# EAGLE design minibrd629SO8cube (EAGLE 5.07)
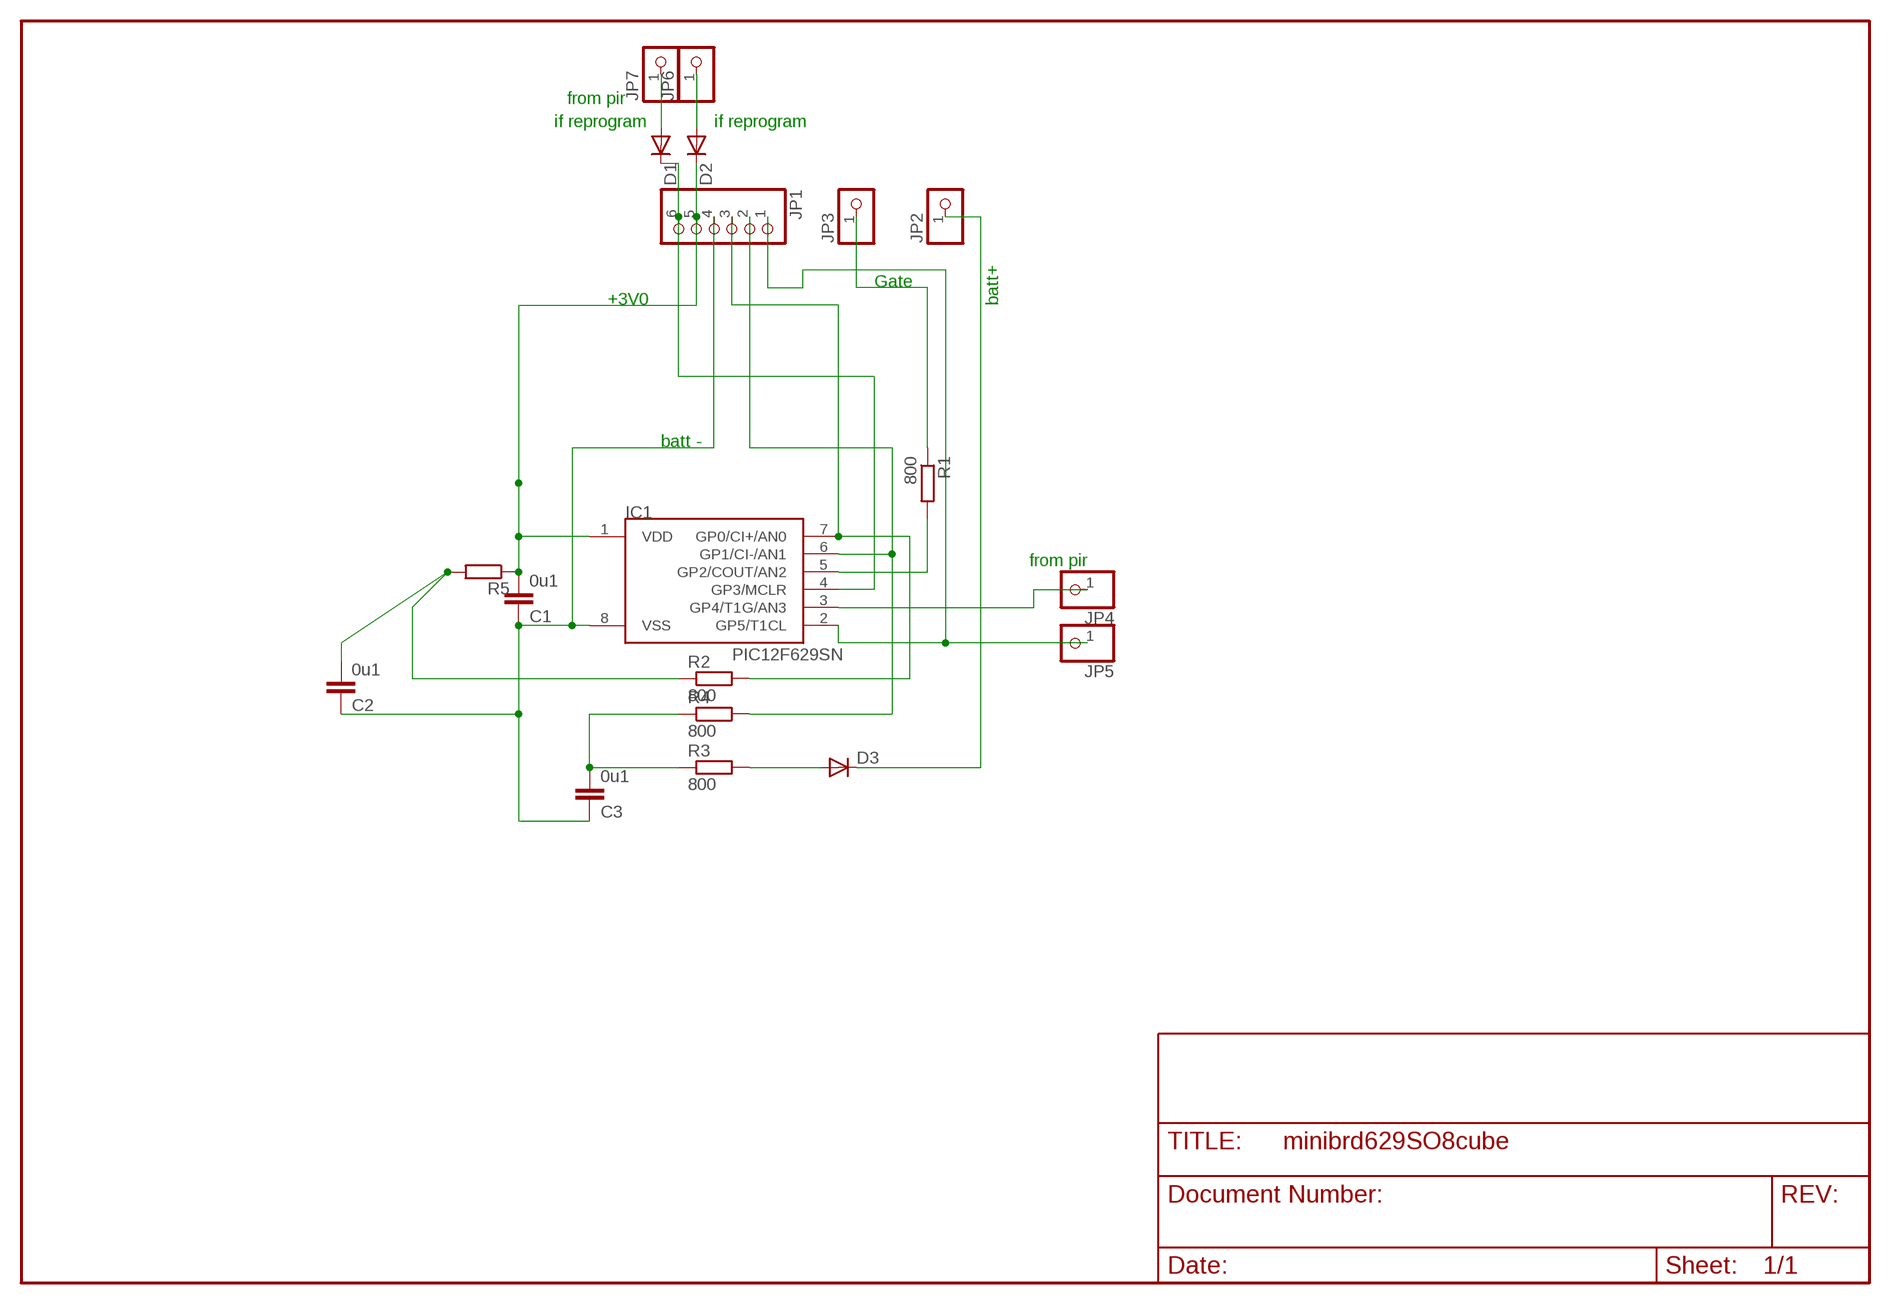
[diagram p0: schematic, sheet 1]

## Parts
C1  0u1  C-EUC1206  [C1206]
C2  0u1  C-EUC1206  [C1206]
C3  0u1  C-EUC1206  [C1206]
D1  DIODE-MINIMELF  [MINIMELF]
D2  DIODE-MINIMELF  [MINIMELF]
D3  DIODE-MINIMELF  [MINIMELF]
IC1  PIC12F629SN  [SO-08]
JP1  PINHD-1X6  [1X06BOX]
JP2  PINHD-1X1  [1X01]
JP3  PINHD-1X1  [1X01]
JP4  PINHD-1X1  [1X01]
JP5  PINHD-1X1  [1X01]
JP6  PINHD-1X1  [1X01]
JP7  PINHD-1X1  [1X01]
R1  800  R-EU_M1206  [M1206]
R2  800  R-EU_M1206  [M1206]
R3  800  R-EU_M1206  [M1206]
R4  800  R-EU_M1206  [M1206]
R5  R-EU_0613/5V  [P0613V]

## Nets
N$1: IC1.5(GP2/COUT/AN2) R1.2
N$2: D1.A JP7.1
N$3: D2.A JP6.1
N$4: IC1.7(GP0/CI+/AN0) JP1.3 R2.2
N$5: JP3.1 R1.1
N$6: C2.2 R2.1 R5.2
N$7: C3.2 R3.1 R4.1
N$8: IC1.6(GP1/CI-/AN1) JP1.2 R4.2
N$9: D3.A R3.2
N$11: IC1.2(GP5/T1CL) JP1.1 JP5.1
N$13: IC1.3(GP4/T1G/AN3) JP4.1
PIR: D1.C IC1.4(GP3/MCLR) JP1.6
V3: C1.2 D2.C IC1.1(VDD) JP1.5 R5.1
V+: D3.C JP2.1
V-: C1.1 C2.1 C3.1 IC1.8(VSS) JP1.4

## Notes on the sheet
- from pir
- if reprogram | if reprogram
- Gate
- +3V0 | batt+
- batt -
- from pir

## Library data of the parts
C1-C3 = rcl:C-EU: CAPACITOR, European symbol
D1-D3 = diode-1:DIODE-: DIODE
IC1 = microchip-3:PIC12F6*: uPC nW 1k Program Flash memory 2x Timer Comparator 10b A/D converter/ 4xIN
JP1 = pinhead:PINHD-1X6: PIN HEADER
JP2-JP7 = pinhead:PINHD-1X1: PIN HEADER
R1-R5 = rcl:R-EU_: RESISTOR, European symbol

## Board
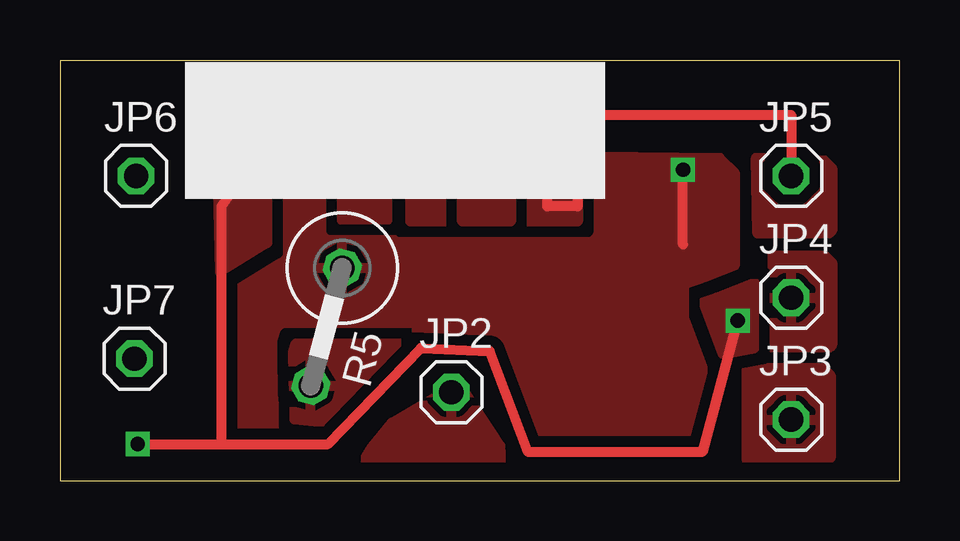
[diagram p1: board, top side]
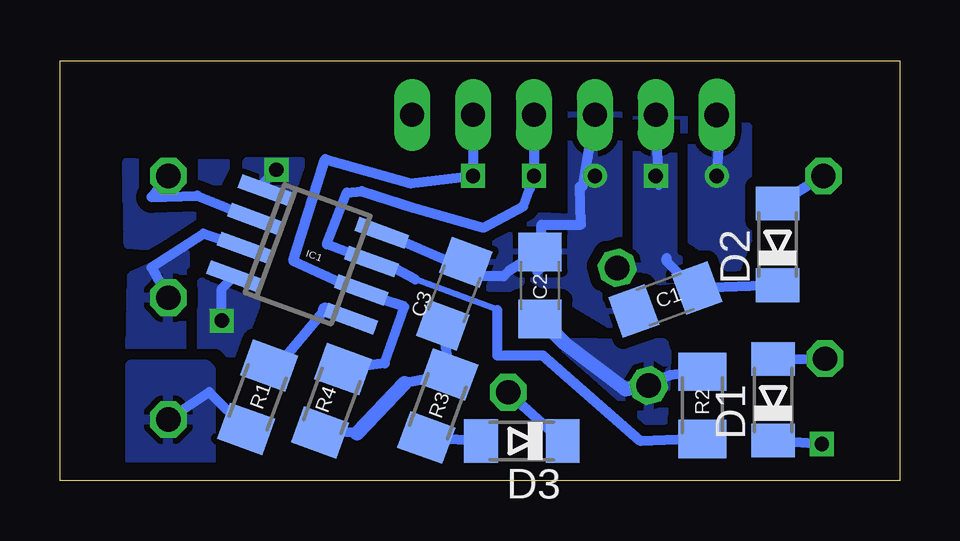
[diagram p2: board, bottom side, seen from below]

Size 35 x 17.5 mm. Coordinates in mm from the lower left corner, seen from the top.
Outline: 0,0 35,0 35,17.5 0,17.5 0,0
Copper layers (1*16): Top 0.035mm / dielectric 1.5mm / Bottom 0.035mm
Design rules "default *": minimum track width 10mil, minimum drill 24mil, track to track 18mil, track to pad 18mil, pad to pad 8mil, via to via 8mil, smd to smd 8mil, copper to edge 30mil, drill to drill 8mil, minimum pad ring 10mil, minimum via ring 8mil, stop-mask expansion 4mil, vias tented up to drill 0mil, thermal gap 10mil

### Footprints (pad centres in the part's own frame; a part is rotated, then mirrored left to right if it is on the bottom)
C1206 = smd 1.6 x 1.8: 1 -1.4,0; 2 1.4,0
MINIMELF = smd 1.4 x 1.8: A 1.7,0; C -1.7,0
SO-08 = smd 0.6 x 2.2: 1 -1.905,-2.6; 2 -0.635,-2.6; 3 0.635,-2.6; 4 1.905,-2.6; 5 1.905,2.6; 6 0.635,2.6; 7 -0.635,2.6; 8 -1.905,2.6
1X06BOX = drill 1 long: 1 -6.35,0; 2 -3.81,0; 3 -1.27,0; 4 1.27,0; 5 3.81,0 | drill 1.016 long: 6 6.35,0
1X01 = drill 1.016 octagon: 1 0,0
M1206 = smd 1.6 x 2: 1 -1.4,0; 2 1.4,0
P0613V = drill 1.016 octagon: 1 -2.54,0; 2 2.54,0

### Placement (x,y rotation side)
C1  9.76,7.54 20 bottom
C2  14.99,8.13 270 bottom
C3  18.56,7.79 250 bottom
D1  5.27,3.37 90 bottom
D2  5.08,9.84 90 bottom
D3  15.75,1.65 180 bottom
IC1  24.67,9.43 250 bottom
JP1  13.97,15.24 180 top
JP2  16.32,3.68 0 top
JP3  30.48,2.54 0 top
JP4  30.48,7.62 0 top
JP5  30.48,12.7 0 top
JP6  3.17,12.7 0 top
JP7  3.11,5.08 0 top
R1  26.76,3.47 70 bottom
R2  8.22,3.14 270 bottom
R3  19.25,3.1 250 bottom
R4  23.67,3.33 70 bottom
R5  11.11,6.41 255 top

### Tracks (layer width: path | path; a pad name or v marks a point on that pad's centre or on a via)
N$1
  Bottom 0.406: R1.2 25.97,4.7 23.94,7.11
  Bottom 0.61: 23.94,7.11 IC1.5
N$2
  Bottom 0.406: D1.A JP7.1
N$3
  Bottom 0.406: D2.A JP6.1
N$4  (via drill 0.6)
  Top 0.406: v15.24,12.7 JP1.3
  Bottom 0.254: 16.76,7.11 20.19,8.38
  Bottom 0.406: 20.19,8.38 21.02,8.83 21.91,9.08 IC1.7 23.88,9.84 23.05,12 22.42,12.06 20.26,11.37 17.34,10.54 15.68,11.43 15.43,12.13 v15.24,12.7 | 16.76,7.11 16.76,5.21 14.86,5.21 10.79,1.65 R2.2 | JP1.3 15.24,12.89
  pour Top (rank 3): 14.61,15.24 16.26,15.24 16.26,10.79 14.61,10.79
N$5
  Bottom 0.406: R1.1 28.77,3.69 JP3.1
  pour Bottom: 28.89,4.83 32.07,4.83 32.07,0.76 28.7,0.76 28.7,4.64
  pour Top (rank 2): 28.64,4.7 31.81,4.7 32.13,4.38 32.13,0.95 31.94,0.76 28.7,0.76 28.64,0.83
N$6
  Bottom 0.406: R2.1 9.59,4.38 R5.2
  Bottom 0.61: C2.2 13.97,5.71 11.43,3.81 R5.2
  pour Bottom (rank 2): 9.84,5.71 14.16,5.71 14.73,4.7 10.99,2.41 9.78,2.54 9.72,5.33
  pour Top: 9.84,5.71 14.16,5.71 14.73,4.7 10.99,2.41 9.78,2.54 9.72,5.33
N$7
  Bottom 0.406: C3.2 18.73,4.32 R3.1 20.64,4.06 | R4.1 24,2.1 22.61,1.97
  Bottom 0.61: 20.64,4.06 22.61,1.97
N$8  (via drill 0.6)
  Top 0.406: v17.78,12.7 JP1.2
  Bottom 0.406: 22.54,7.87 IC1.6 | 22.54,7.87 23.05,8.13 25.27,9.14 23.94,13.4 20.38,12.38 v17.78,12.7 | 22.54,7.87 20.64,7.24 21.46,4.89 23.3,4.64 R4.2 | JP1.2 17.78,12.51
  pour Top (rank 2): 16.76,15.24 18.8,15.24 18.8,10.79 16.76,10.79
N$9
  Bottom 0.406: D3.A R3.2
N$11
  Top 0.406: JP1.1 20.32,11.43 21.59,11.43 21.59,15.24 30.48,15.24 JP5.1
  Bottom 0.406: IC1.2 29.27,11.87 31.18,11.81 JP5.1
  pour Top (rank 3): 19.3,15.24 21.59,15.24 21.59,10.79 19.3,10.79
N$13
  Bottom 0.406: IC1.3 29.02,10.29 31.18,8.89 JP4.1
  pour Bottom (rank 3): 30.61,9.14 32,8.51 32.07,5.52 29.78,5.52 29.78,9.46
  pour Top (rank 3): 29.72,9.4 31.88,9.4 32.19,9.08 32.19,5.65 32.07,5.52 29.72,5.52 29.65,5.59
N$14
  pour Bottom: 28.07,13.21 29.08,11.11 31.43,9.78 32.13,9.84 32.19,13.27 31.24,13.21
  pour Top: 29.02,13.46 31.75,13.46 32.19,13.02 32.19,10.41 32.07,10.29 29.08,10.29
PIR  (via drill 0.6)
  Top 0.406: 6.73,1.52 6.73,11.43 v7.62,12.7 | 6.73,1.52 11.18,1.52 15.05,5.52 17.91,5.4 19.49,1.21 26.8,1.21 v28.26,6.67 | v3.24,1.52 6.73,1.52
  Bottom 0.406: IC1.4 27.77,8.49 28.26,8 v28.26,6.67 | JP1.6 7.43,15.18 v7.62,12.7 | v3.24,1.52 D1.C
  pour Bottom (rank 2): 26.8,7.43 27.62,5.27 29.08,5.52 29.08,8.26 27.37,7.62
  pour Bottom: 6.35,14.73 8.64,14.8 8.64,10.03 7.49,9.21 6.86,8.7 6.35,10.03
  pour Top: 26.8,7.43 27.62,5.27 28.96,5.52 28.96,8.26 27.37,7.62
  pour Top: 6.54,14.8 8.64,14.73 8.64,9.91 7.49,9.21 6.67,8.7
V3  (via drill 0.6)
  Top 0.406: 25.97,9.84 v25.97,12.95
  Bottom 0.406: IC1.1 26.46,12.46 v25.97,12.95 | 9.72,9.27 9.72,9.14 8.59,8.02 C1.2 D2.C | JP1.5 10.03,12.32 v10.16,12.7
  pour Bottom (rank 2): 25.34,12.13 24.96,13.27 27.18,13.27 27.3,12.76
  pour Bottom (rank 2): 8.89,14.99 8.89,8.45 12.32,8.06 11.43,9.91 11.43,14.99
  pour Top (rank 4): 22.42,13.53 27.5,13.46 28.13,12.83 28.13,8.95 27.94,8.76 27.62,8.76 27.88,0.57 18.86,0.7 13.91,6.41 11.75,6.41 11.05,0.95 6.48,0.95 6.48,8.32 9.33,14.92 11.05,14.73 11.05,10.41 21.97,10.41
V+
  Bottom 0.406: D3.C JP2.1
  pour Top: 13.02,1.4 13.84,2.41 16.64,4.06 18.35,1.46 18.41,0.38 12.45,0.44
V-  (via drill 0.6)
  Bottom 0.406: IC1.8 17.97,8.76 C3.1 18.08,9.06 17.53,8.51 16.51,8.51 16.3,8.71 C2.1 15.1,8.71 14.92,8.89 14.92,10.67 13.27,10.67 13.33,12.26 13.21,12.26 JP1.4
  other vias: 12.7,12.7
  pour Bottom (isolate 0.406): 11.68,15.56 13.72,15.56 13.72,10.99 16.26,11.11 17.21,10.22 17.21,8.13 17.34,8 16,8 15.75,8.26 15.75,8.64 11.68,6.22
  pour Top (isolate 0.406): 13.72,15.3 13.72,10.79 11.68,10.79 11.68,15.11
